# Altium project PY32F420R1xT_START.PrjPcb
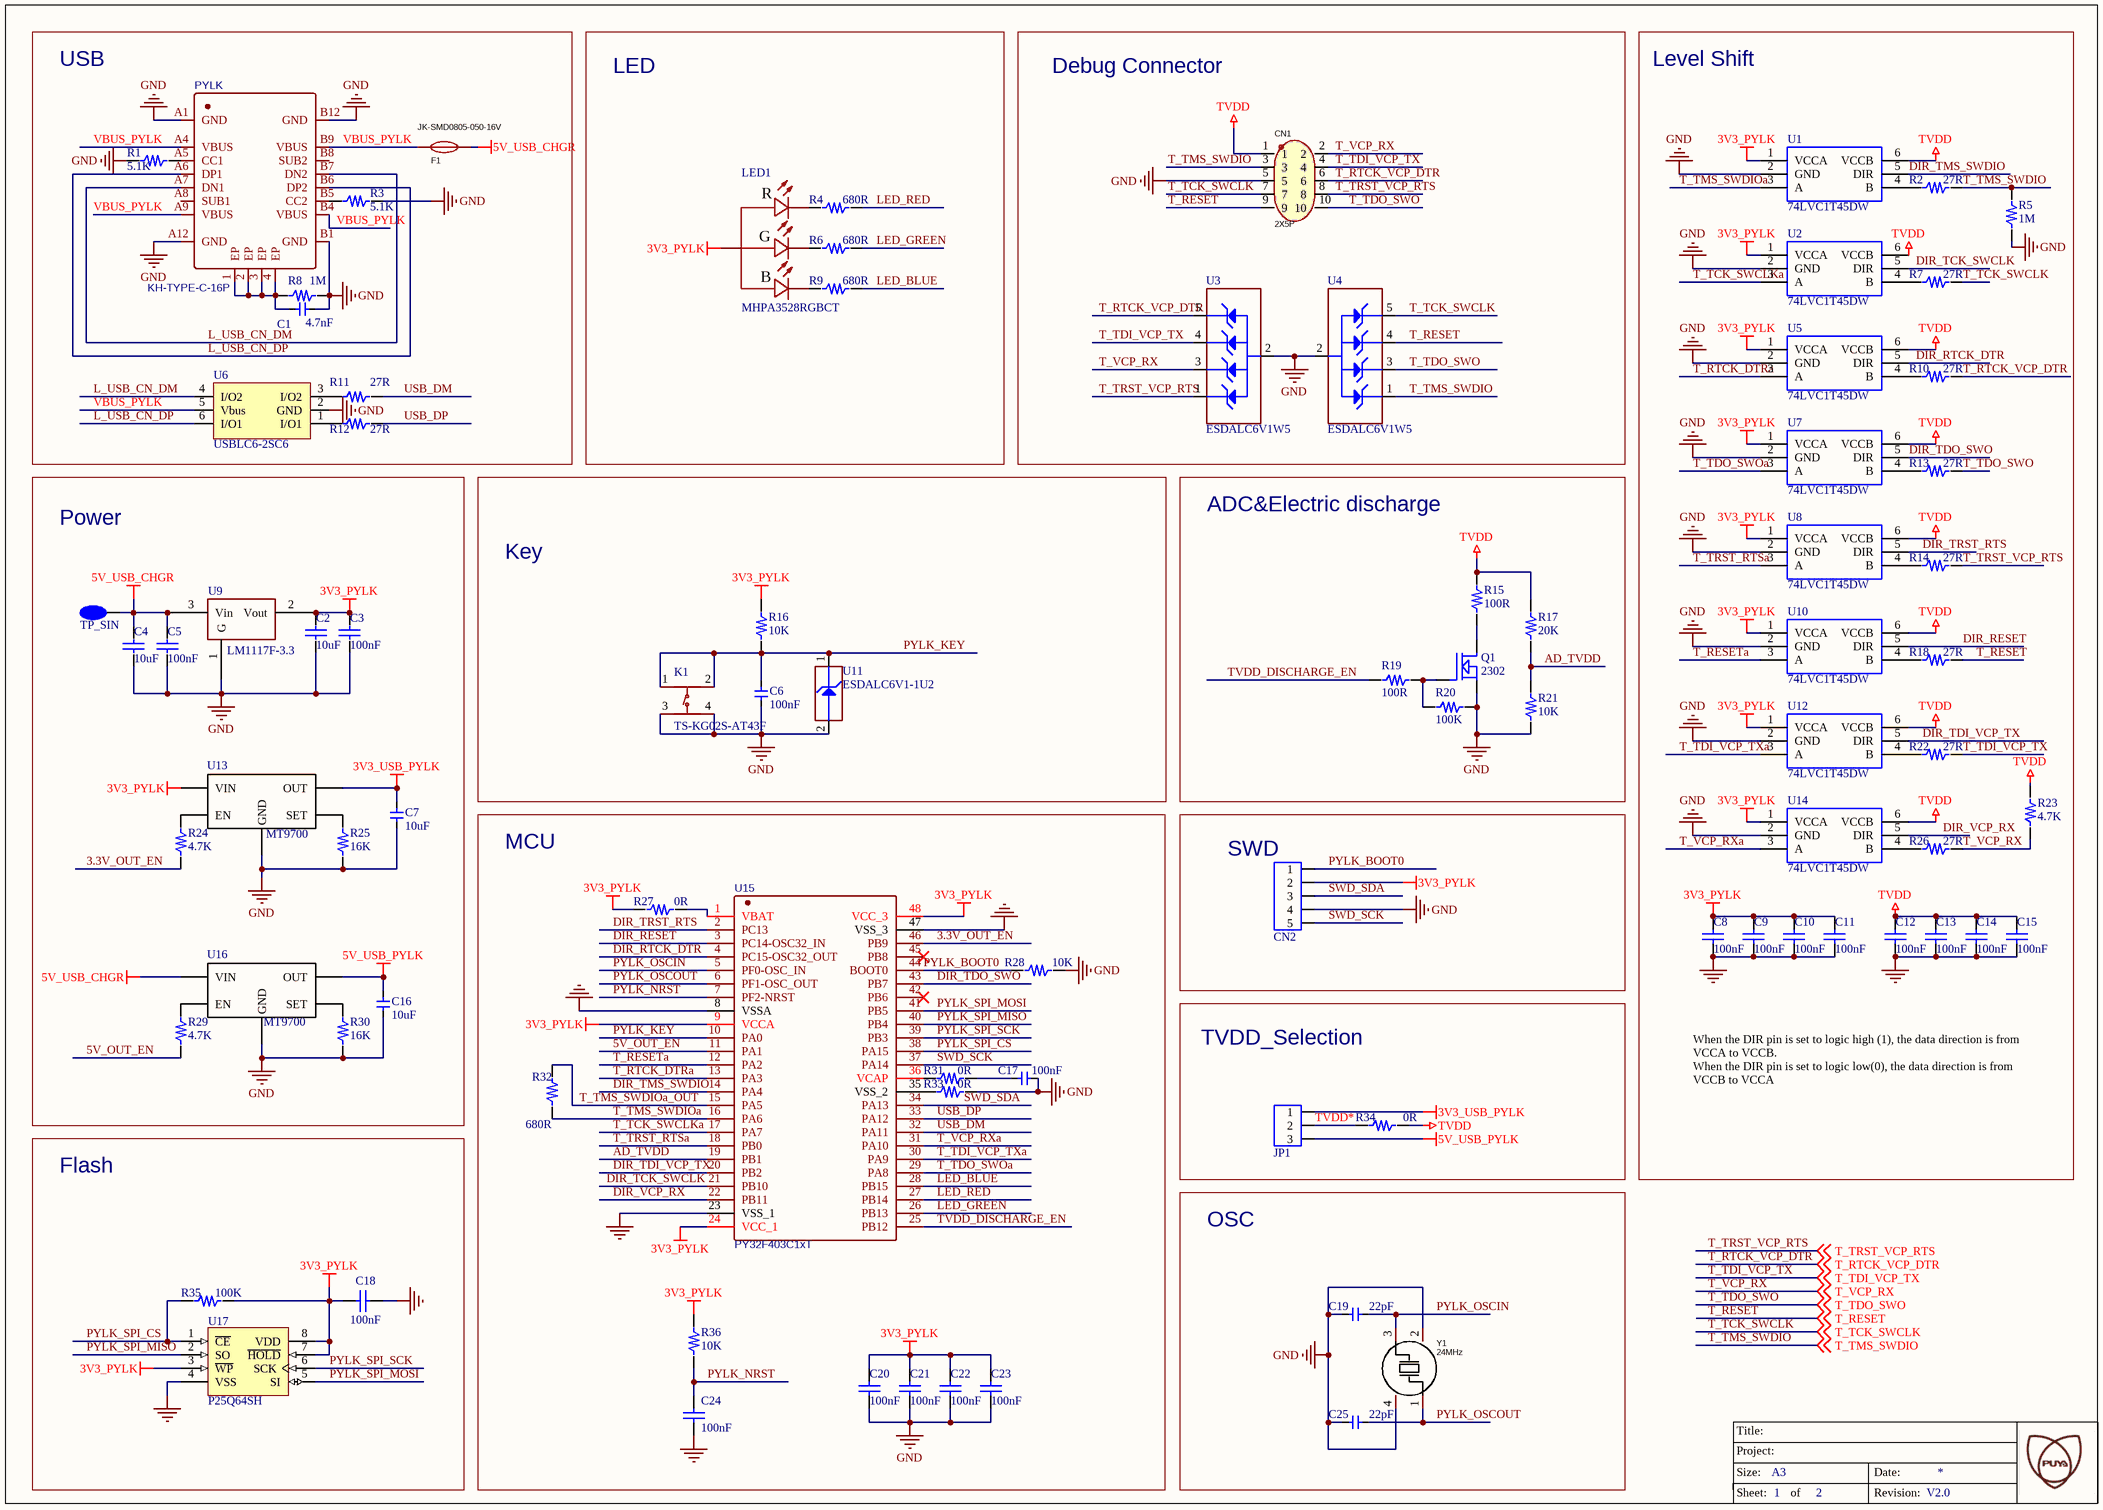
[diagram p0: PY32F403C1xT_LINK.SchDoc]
2 sheets, 144 parts. Net scope: global (net labels, ports and power ports of the same name join across sheets).
Board file: PY32F420R1xT_START.PcbDoc
Sheets:
  PY32F403C1xT_LINK.SchDoc
  PY32F420R1xT_START.SchDoc

## Sheet PY32F403C1xT_LINK.SchDoc: =DocumentName
size A3; Revision: V2.0; SheetNumber: 1; SheetTotal: 2; Project: PY32F420R1xT_START.PrjPcb

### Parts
5V_USB_CHGR  TP_SIN  [TP_SIN]
C1  4.7nF  [C0603]
C2  10uF  [C0805]
C3  100nF  [C0603]
C4  10uF  [C0805]
C5  100nF  [C0603]
C6  100nF  [C0603]
C7  10uF  [C0805]
C8  100nF  [C0603]
C9  100nF  [C0603]
C10  100nF  [C0603]
C11  100nF  [C0603]
C12  100nF  [C0603]
C13  100nF  [C0603]
C14  100nF  [C0603]
C15  100nF  [C0603]
C16  10uF  [C0805]
C17  100nF  [C0603]
C18  100nF  [C0603]
C19  22pF  [C0603]
C20  100nF  [C0603]
C21  100nF  [C0603]
C22  100nF  [C0603]
C23  100nF  [C0603]
C24  100nF  [C0603]
C25  22pF  [C0603]
CN1  2X5P  [HDR2X5]
CN2  CON5  [CON5]  (value not drawn)
F1  JK-SMD0805-050-16V  [F0805]
JP1  CON3  [CON3]  (value not drawn)
K1  TS-KG02S-AT43F  [SW-SMD_4P-L6.0-W6.0-P4.50-LS8.5]
LED1  MHPA3528RGBCT  [LED-ARRAY-SMD_4P-L3.5-W2.8-TL]
PYLK  KH-TYPE-C-16P  [USB-C-SMD_KH-TYPE-C-16P]
Q1  2302  [SOT23]
R1  5.1K  [R0603]
R2  27R  [R0603]
R3  5.1K  [R0603]
R4  680R  [R0603]
R5  1M  [R0603]
R6  680R  [R0603]
R7  27R  [R0603]
R8  1M  [R0603]
R9  680R  [R0603]
R10  27R  [R0603]
R11  27R  [R0603]
R12  27R  [R0603]
R13  27R  [R0603]
R14  27R  [R0603]
R15  100R  [R0805]
R16  10K  [R0603]
R17  20K  [R0603]
R18  27R  [R0603]
R19  100R  [R0603]
R20  100K  [R0603]
R21  10K  [R0603]
R22  27R  [R0603]
R23  4.7K  [R0603]
R24  4.7K  [R0603]
R25  16K  [R0603]
R26  27R  [R0603]
R27  0R  [JP2_SMD]
R28  10K  [R0603]
R29  4.7K  [R0603]
R30  16K  [R0603]
R31  0R  [JP2_SMD]
R32  680R  [R0603]
R33  0R  [JP2_SMD]
R34  0R  [JP2_SMD]
R35  100K  [R0603]
R36  10K  [R0603]
U1  74LVC1T45DW  [SOT363]
U2  74LVC1T45DW  [SOT363]
U3  ESDALC6V1W5  [ESD_SOT323-5L]
U4  ESDALC6V1W5  [ESD_SOT323-5L]
U5  74LVC1T45DW  [SOT363]
U6  USBLC6-2SC6  [SOT23-6]
U7  74LVC1T45DW  [SOT363]
U8  74LVC1T45DW  [SOT363]
U9  LM1117F-3.3  [SOT-89-3_L4.5-W2.5-P1.50-LS4.2-BR]
U10  74LVC1T45DW  [SOT363]
U11  ESDALC6V1-1U2  [ESD_ST0201]
U12  74LVC1T45DW  [SOT363]
U13  MT9700  [SOT23-5]
U14  74LVC1T45DW  [SOT363]
U15  PY32F403C1xT  [LQFP-48_L7.0-W7.0-P0.50-LS9.0-BL]
U16  MT9700  [SOT23-5]
U17  P25Q64SH  [SOP-8P]
Y1  24MHz  [CRYSTAL-SMD_4P-L3.2-W2.5-BL]

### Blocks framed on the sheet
USB: C1 F1 PYLK R1 R3 R8 R11 R12 U6
LED: LED1 R4 R6 R9
Debug Connector: CN1 U3 U4
Level Shift: C8-C15 R2 R5 R7 R10 R13 R14 R18 R22 R23 R26 U1 U2 U5 U7 U8 U10 U12 U14
Power: 5V_USB_CHGR C2-C5 C7 C16 R24 R25 R29 R30 U9 U13 U16
Key: C6 K1 R16 U11
ADC&Electric discharge: Q1 R15 R17 R19-R21
MCU: C17 C20-C24 R27 R28 R31-R33 R36 U15
SWD: CN2
TVDD_Selection: JP1 R34
Flash: C18 R35 U17
OSC: C19 C25 Y1

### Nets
3V3_PYLK: C2.2 C3.2 C8.2 C9.2 C10.2 C11.2 C18.2 C20.2 C21.2 C22.2 C23.2 CN2.2 LED1.1(-) R16.2 R27.1 R35.2 R36.2 U1.1(VCCA) U2.1(VCCA) U5.1(VCCA) U7.1(VCCA) U8.1(VCCA) U9.2(Vout) U10.1(VCCA) U12.1(VCCA) U13.5(VIN) U14.1(VCCA) U15.9(VCCA) U15.24(VCC_1) U15.48(VCC_3) U17.3(~{WP}) U17.7(~{HOLD}) U17.8(VDD)
3V3_USB_PYLK: C7.2 JP1.1 U13.1(OUT)
5V_USB_CHGR: 5V_USB_CHGR.1(TP_SIN) C4.2 C5.2 F1.2 U9.3(Vin) U16.5(VIN)
5V_USB_PYLK: C16.2 JP1.3 U16.1(OUT)
GND: C1.1 C2.1 C3.1 C4.1 C5.1 C6.1 C7.1 C8.1 C9.1 C10.1 C11.1 C12.1 C13.1 C14.1 C15.1 C16.1 C17.1 C18.1 C19.1 C20.1 C21.1 C22.1 C23.1 C24.1 C25.1 CN1.5 CN2.4 K1.3 K1.4 PYLK.A1(GND) PYLK.A12(GND) PYLK.B1(GND) PYLK.B12(GND) Q1.2(S) R1.1 R3.2 R5.1 R8.2 R20.1 R21.1 R25.1 R28.2 R30.1 R33.2 U1.2(GND) U2.2(GND) U3.2(GND) U4.2(GND) U5.2(GND) U6.2(GND) U7.2(GND) U8.2(GND) U9.1(G) U10.2(GND) U11.2(GND) U12.2(GND) U13.2(GND) U14.2(GND) U15.8(VSSA) U15.23(VSS_1) U15.47(VSS_3) U16.2(GND) U17.4(VSS) Y1.2(GND) Y1.4(GND)
TVDD: C12.2 C13.2 C14.2 C15.2 CN1.1 R15.2 R17.2 R23.2 R34.2 U1.6(VCCB) U2.6(VCCB) U5.6(VCCB) U7.6(VCCB) U8.6(VCCB) U10.6(VCCB) U12.6(VCCB) U14.6(VCCB)
3.3V_OUT_EN: R24.1 U15.46(PB9)
5V_OUT_EN: R29.1 U15.11(PA1)
AD_TVDD: R17.1 R21.2 U15.19(PB1)
DIR_RESET: U10.5(DIR) U15.3(PC14-OSC32_IN)
DIR_RTCK_DTR: U5.5(DIR) U15.4(PC15-OSC32_OUT)
DIR_TCK_SWCLK: U2.5(DIR) U15.21(PB10)
DIR_TDI_VCP_TX: U12.5(DIR) U15.20(PB2)
DIR_TDO_SWO: U7.5(DIR) U15.43(PB7)
DIR_TMS_SWDIO: U1.5(DIR) U15.14(PA4)
DIR_TRST_RTS: U8.5(DIR) U15.2(PC13)
DIR_VCP_RX: U14.5(DIR) U15.22(PB11)
L_USB_CN_DM: PYLK.A7(DN1) PYLK.B7(DN2) U6.4(I/O2)
L_USB_CN_DP: PYLK.A6(DP1) PYLK.B6(DP2) U6.6(I/O1)
LED_BLUE: R9.2 U15.28(PB15)
LED_GREEN: R6.2 U15.26(PB13)
LED_RED: R4.2 U15.27(PB14)
PYLK_BOOT0: CN2.1 R28.1 U15.44(BOOT0)
PYLK_KEY: C6.2 K1.1 K1.2 R16.1 U11.1(IO1) U15.10(PA0)
PYLK_NRST: C24.2 R36.1 U15.7(PF2-NRST)
PYLK_OSCIN: C19.2 U15.5(PF0-OSC_IN) Y1.3(OSC2)
PYLK_OSCOUT: C25.2 U15.6(PF1-OSC_OUT) Y1.1(OSC1)
PYLK_SPI_CS: R35.1 U15.38(PA15) U17.1(~{CE})
PYLK_SPI_MISO: U15.40(PB4) U17.2(SO)
PYLK_SPI_MOSI: U15.41(PB5) U17.5(SI)
PYLK_SPI_SCK: U15.39(PB3) U17.6(SCK)
SWD_SCK: CN2.5 U15.37(PA14)
SWD_SDA: CN2.3 U15.34(PA13)
T_RESET: CN1.9 R18.2 U4.4(IO3) ; off-sheet T_RESET
T_RESETa: U10.3(A) U15.12(PA2)
T_RTCK_DTRa: U5.3(A) U15.13(PA3)
T_RTCK_VCP_DTR: CN1.6 R10.2 U3.5(IO4) ; off-sheet T_RTCK_VCP_DTR
T_TCK_SWCLK: CN1.7 R7.2 U4.5(IO4) ; off-sheet T_TCK_SWCLK
T_TCK_SWCLKa: U2.3(A) U15.17(PA7)
T_TDI_VCP_TX: CN1.4 R22.2 U3.4(IO3) ; off-sheet T_TDI_VCP_TX
T_TDI_VCP_TXa: U12.3(A) U15.30(PA9)
T_TDO_SWO: CN1.10 R13.2 U4.3(IO2) ; off-sheet T_TDO_SWO
T_TDO_SWOa: U7.3(A) U15.29(PA8)
T_TMS_SWDIO: CN1.3 R2.2 R5.2 U4.1(IO1) ; off-sheet T_TMS_SWDIO
T_TMS_SWDIOa: R32.1 U1.3(A) U15.16(PA6)
T_TMS_SWDIOa_OUT: R32.2 U15.15(PA5)
T_TRST_RTSa: U8.3(A) U15.18(PB0)
T_TRST_VCP_RTS: CN1.8 R14.2 U3.1(IO1) ; off-sheet T_TRST_VCP_RTS
T_VCP_RX: CN1.2 R23.1 R26.2 U3.3(IO2) ; off-sheet T_VCP_RX
T_VCP_RXa: U14.3(A) U15.31(PA10)
TVDD*: JP1.2 R34.1
TVDD_DISCHARGE_EN: R19.2 U15.25(PB12)
USB_DM: R11.2 U15.32(PA11)
USB_DP: R12.2 U15.33(PA12)
VBUS_PYLK: F1.1 PYLK.A4(VBUS) PYLK.A9(VBUS) PYLK.B4(VBUS) PYLK.B9(VBUS) U6.5(Vbus)
NetC1_2: C1.2 PYLK.1(EP) PYLK.2(EP) PYLK.3(EP) PYLK.4(EP) R8.1
NetC17_2: C17.2 R31.2
NetLED1_2: LED1.2(-) R9.1
NetLED1_3: LED1.3(-) R6.1
NetLED1_4: LED1.4(-) R4.1
NetPYLK_A5: PYLK.A5(CC1) R1.2
NetPYLK_B5: PYLK.B5(CC2) R3.1
NetQ1_1: Q1.1(G) R19.1 R20.2
NetQ1_3: Q1.3(D) R15.1
NetR2_1: R2.1 U1.4(B)
NetR7_1: R7.1 U2.4(B)
NetR10_1: R10.1 U5.4(B)
NetR11_1: R11.1 U6.3(I/O2)
NetR12_1: R12.1 U6.1(I/O1)
NetR13_1: R13.1 U7.4(B)
NetR14_1: R14.1 U8.4(B)
NetR18_1: R18.1 U10.4(B)
NetR22_1: R22.1 U12.4(B)
NetR24_2: R24.2 U13.4(EN)
NetR25_2: R25.2 U13.3(SET)
NetR26_1: R26.1 U14.4(B)
NetR27_2: R27.2 U15.1(VBAT)
NetR29_2: R29.2 U16.4(EN)
NetR30_2: R30.2 U16.3(SET)
NetR31_1: R31.1 U15.36(VCAP)
NetR33_1: R33.1 U15.35(VSS_2)

Not connected (* = marked no-connect by the designer): PYLK A8(SUB1) B8(SUB2); U15 42(PB6)* 45(PB8)*

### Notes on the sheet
- When the DIR pin is set to logic high (1), the data direction is from VCCA to VCCB.
  When the DIR pin is set to logic low(0), the data direction is from VCCB to VCCA

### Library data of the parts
C1 C3 C5 C6 C17 C19 C25 = C0603: PCB DECAL: 0603
C2 C4 C7 C16 = C0805: PCB DECAL: 0805
C8-C15 C18 C20-C24 = 贴片高压陶瓷电容: Capacitor (Semiconductor SIM Model); 器件封装(外观): 0603; Value: 104
CN1 = 2X5P: Manufacturer: XFCN(兴飞); Symbol: PZ254V-12-10P; Add into BOM: yes; Pitch: 2.54mm; Circluar Pins/Square Pins: 方针
F1 = JK-SMD0805-050-16V: Manufacturer: JK(金科); Add into BOM: yes; Voltage - Max: 6V; Current - Max: 100A; Hold Current: 500mA; Trip Current: 1A; Power Dissipation: 600mW; Resistance - Initial (Ri) (Min): 150mΩ; Resistance - Post Trip (R1) (Max): 850mΩ; Time to Trip(Max): 100ms
K1 = TS-KG02S-AT43F: Manufacturer: HANBO(汉博); Add into BOM: yes; Circuit: 单刀单掷; Actuator Style: 圆形按钮; Operating Force: 250gf; Switch Length: 6mm; Switch Height: 4.3mm; Strike Gundam: 不带; Contact Current: 50mA; Voltage Rating (DC): 12V; Insulation Resistance: 100MΩ; Actuator/Cap Color: 黑色; Pin Style: 鸥翼型
LED1 = MHPA3528RGBCT: Manufacturer: MEIHUA(美华); Add into BOM: yes
PYLK = KH-TYPE-C-16P: BOM_Manufacturer: Shenzhen Kinghelm Elec; Contributor: LCSC
Q1 = MOSFET N: Value: SI2302
R1-R14 R16-R24 R26-R29 R31-R36 = R0603: PCB DECAL: 0603
R15 = R0805: PCB DECAL: 0805
R25 R30 = R0603_7: 0603WAF1602T5E 16KΩ(1602) ±1%; PCB DECAL: 0603
U3 U4 = ESDALC6V1W5: Dual Transil array for ESD protection; Internal_Part_Number: MCD-00136; Part_Type: Diode; Manufacturer: STMICROELECTRONICS; ECCN_US: EAR99; ECCN_EU: NEC; Provided_By: Subcon; Initial_Board_Reference: MB1262
U6 = USBLC6-2SC6: Function: ESD EMI fliter
U11 = ESDALC6V1-1U2: ESD protection 6V1; Internal_Part_Number: MCD-00170; Part_Type: Diode; Manufacturer: STMICROELECTRONICS; ECCN_US: EAR99; ECCN_EU: NEC; Provided_By: Subcon; Initial_Board_Reference: MB1274
U15 = PY32F403C1xT: LQFP48; BOM_Manufacturer: PUYA(普冉)
U17 = SST25VF010: Value: SST25VF020B; 器件封装(外观): SOP8
Y1 = ABM8AIG-24.000MHZ-82Z-T: ±20ppm , 12.5pF , T_use: -40°C~125°C; Manufacturer: ABRACON; Add into BOM: yes; External load capacitor: 8pF; Frequency Stability(Full temperature range): ±50ppm; Equivalent Series Resistance (ESR): 50Ω

## Sheet PY32F420R1xT_START.SchDoc: =DocumentName
size A3; Revision: V2.0; SheetNumber: 2; SheetTotal: 2; Project: PY32F420R1xT_START.PrjPcb
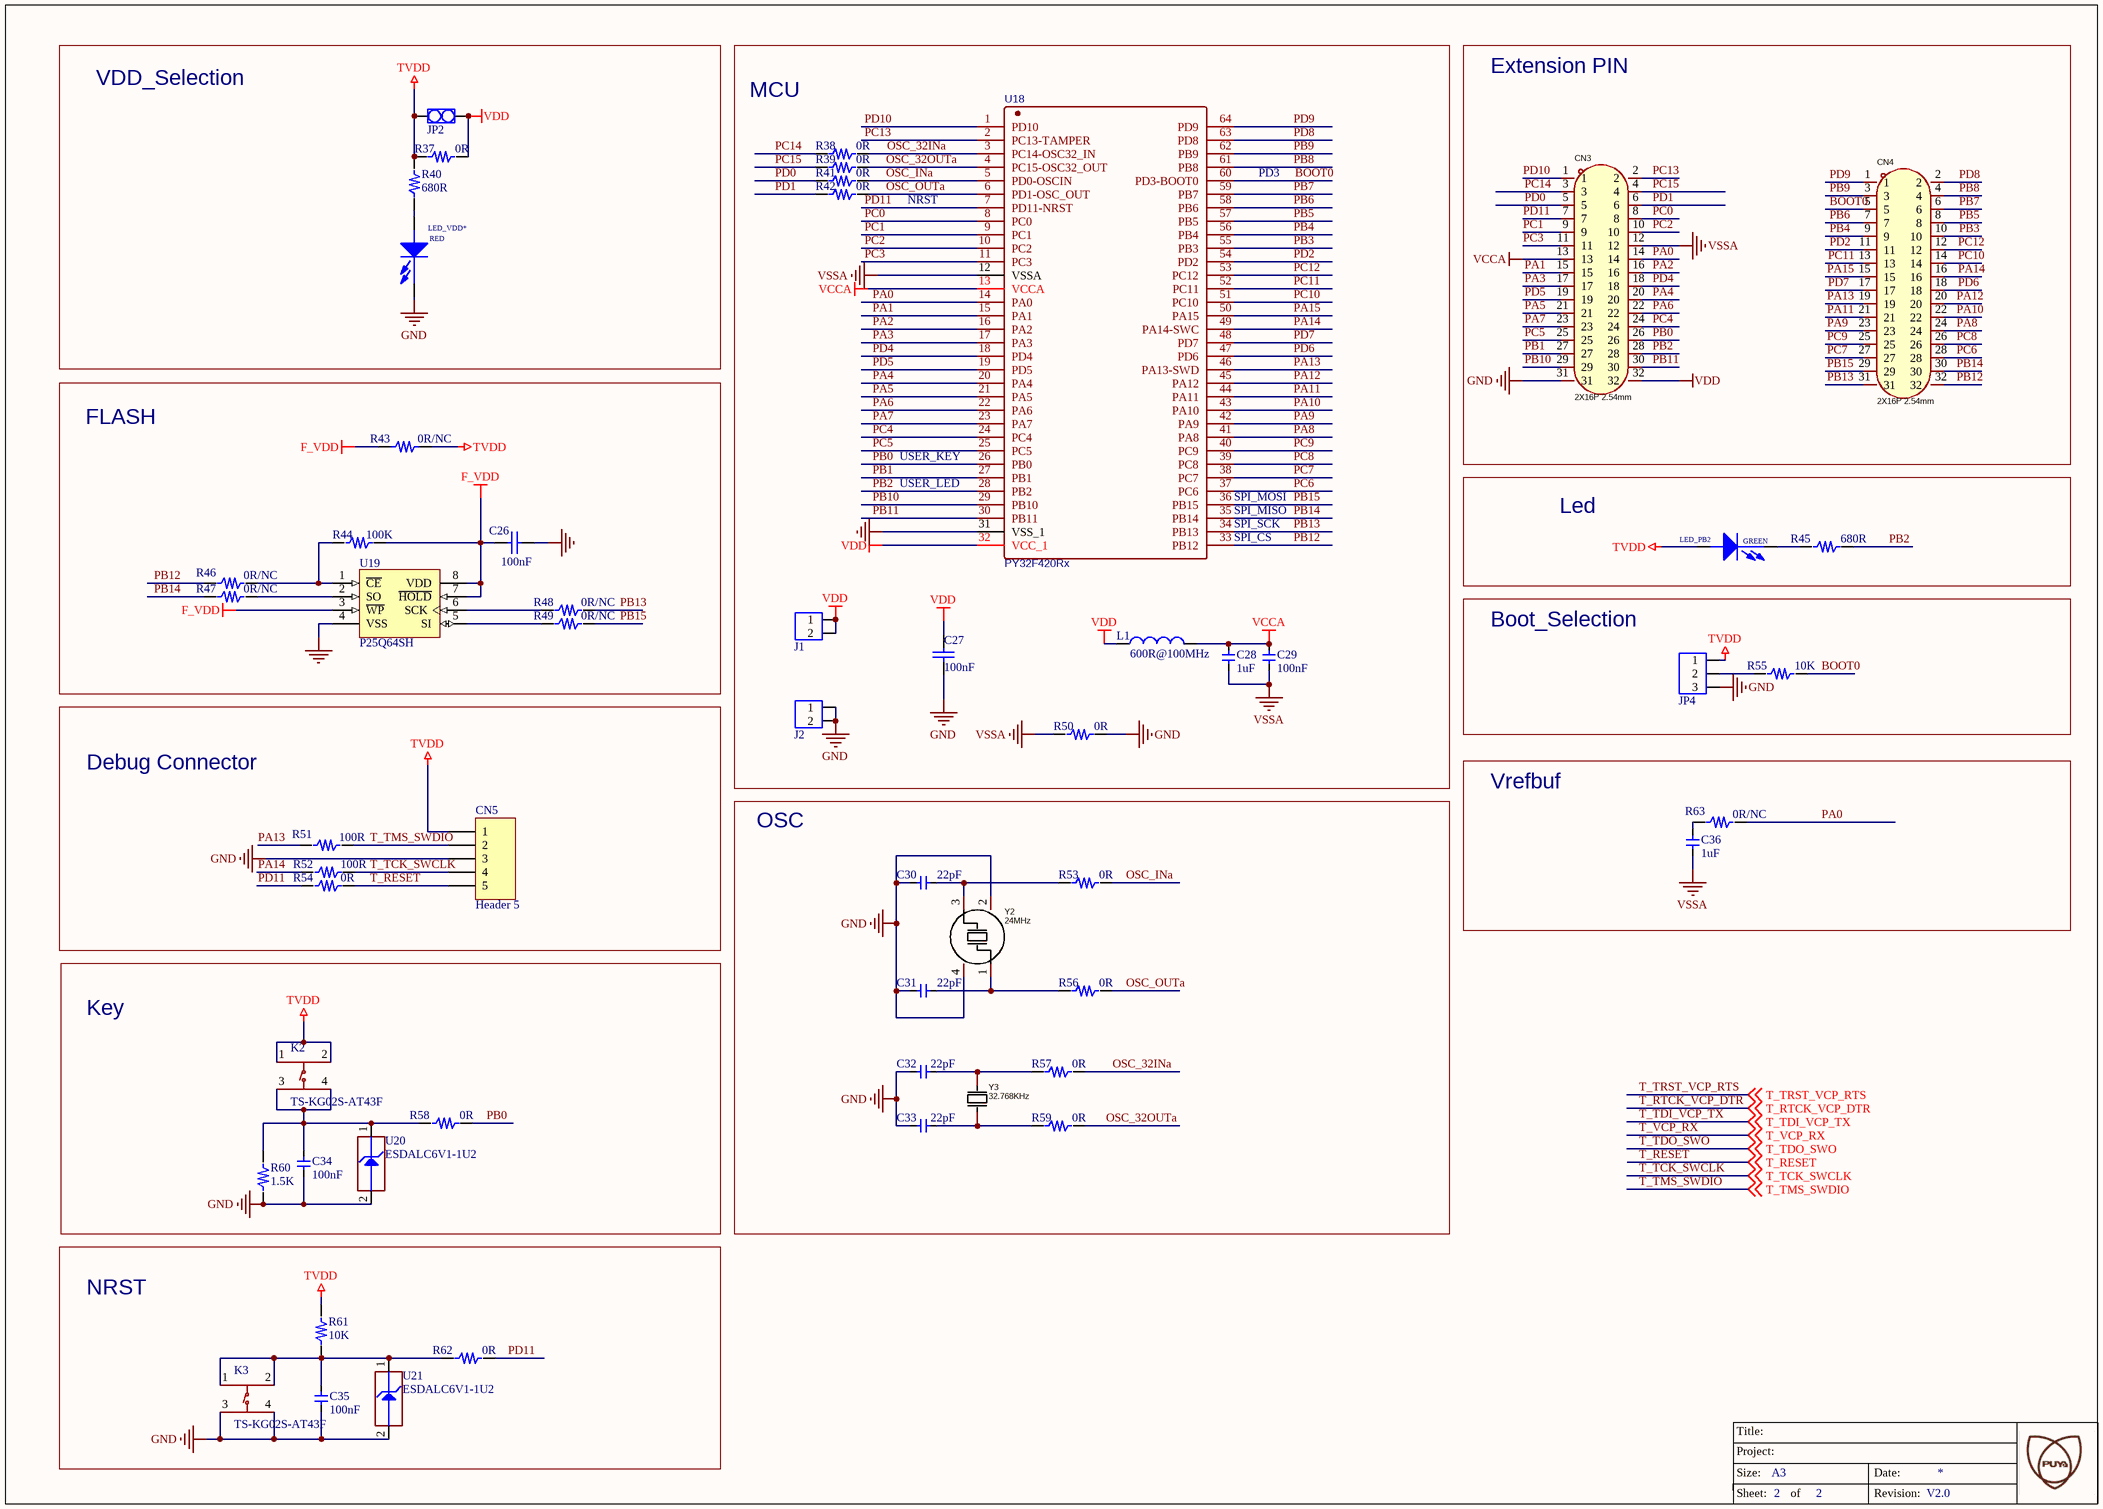
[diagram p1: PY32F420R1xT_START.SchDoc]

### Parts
C26  100nF  [C0603]
C27  100nF  [C0603]
C28  1uF  [C0603]
C29  100nF  [C0603]
C30  22pF  [C0603]
C31  22pF  [C0603]
C32  22pF  [C0603]
C33  22pF  [C0603]
C34  100nF  [C0603]
C35  100nF  [C0603]
C36  1uF  [C0603]
CN3  2X16P 2.54mm  [HDR-TH_32P-P2.54-V-M-R2-C16-S2.54-3]
CN4  2X16P 2.54mm  [HDR-TH_32P-P2.54-V-M-R2-C16-S2.54-3]
CN5  Header 5  [HDR1X5]
J1  CON2  [CON2]  (value not drawn)
J2  CON2  [CON2]  (value not drawn)
JP2  CON2  [CON2]  (value not drawn)
JP4  CON3  [CON3]  (value not drawn)
K2  TS-KG02S-AT43F  [SW-SMD_4P-L6.0-W6.0-P4.50-LS8.5]
K3  TS-KG02S-AT43F  [SW-SMD_4P-L6.0-W6.0-P4.50-LS8.5]
L1  value 600R@100MHz  [L0603]  (hidden comment: BEAD)
LED_PB2  GREEN  [0603_LED]
LED_VDD*  RED  [0603_LED]
R37  0R  [JP2_SMD]
R38  0R  [JP2_SMD]
R39  0R  [JP2_SMD]
R40  680R  [R0603]
R41  0R  [JP2_SMD]
R42  0R  [JP2_SMD]
R43  0R/NC  [JP2_SMD]
R44  100K  [R0603]
R45  680R  [R0603]
R46  0R/NC  [JP2_SMD]
R47  0R/NC  [JP2_SMD]
R48  0R/NC  [JP2_SMD]
R49  0R/NC  [JP2_SMD]
R50  0R  [R0603]
R51  100R  [JP2_SMD]
R52  100R  [JP2_SMD]
R53  0R  [JP2_SMD]
R54  0R  [JP2_SMD]
R55  10K  [R0603]
R56  0R  [JP2_SMD]
R57  0R  [JP2_SMD]
R58  0R  [JP2_SMD]
R59  0R  [JP2_SMD]
R60  1.5K  [R0603]
R61  10K  [R0603]
R62  0R  [JP2_SMD]
R63  0R/NC  [JP2_SMD]
U18  PY32F420Rx  [LQFP-64_L10.0-W10.0-P0.50-LS12.0-BL]
U19  P25Q64SH  [SOP-8P]
U20  ESDALC6V1-1U2  [ESD_ST0201]
U21  ESDALC6V1-1U2  [ESD_ST0201]
Y2  24MHz  [CRYSTAL-SMD_4P-L3.2-W2.5-BL]
Y3  32.768KHz  [CRYSTAL-SMD_L3.2-W1.5-1]

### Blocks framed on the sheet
VDD_Selection: JP2 LED_VDD* R37 R40
MCU: C27-C29 J1 J2 L1 R38 R39 R41 R42 R50 U18
Extension PIN: CN3 CN4
FLASH: C26 R43 R44 R46-R49 U19
Led: LED_PB2 R45
Boot_Selection: JP4 R55
Debug Connector: CN5 R51 R52 R54
Vrefbuf: C36 R63
OSC: C30-C33 R53 R56 R57 R59 Y2 Y3
Key: C34 K2 R58 R60 U20
NRST: C35 K3 R61 R62 U21

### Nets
F_VDD: C26.2 R43.2 R44.2 U19.3(~{WP}) U19.7(~{HOLD}) U19.8(VDD)
GND: C26.1 C27.1 C30.1 C31.1 C32.1 C33.1 C34.1 C35.1 CN3.31 CN5.3 J2.1 J2.2 JP4.3 K3.3 K3.4 LED_VDD*.2(CATHODE) R50.2 R60.1 U18.31(VSS_1) U19.4(VSS) U20.2(GND) U21.2(GND) Y2.2(GND) Y2.4(GND)
TVDD: CN5.1 JP2.1 JP4.1 K2.1 K2.2 LED_PB2.1(ANODE) R37.1 R40.2 R43.1 R61.1
VCCA: C28.2 C29.2 CN3.13 L1.2 U18.13(VCCA)
VDD: C27.2 CN3.32 J1.1 J1.2 JP2.2 L1.1 R37.2 U18.32(VCC_1)
VSSA: C28.1 C29.1 C36.1 CN3.12 R50.1 U18.12(VSSA)
BOOT0: CN4.5 R55.2 U18.60(PD3-BOOT0)
OSC_32INa: R38.2 R57.2 U18.3(PC14-OSC32_IN)
OSC_32OUTa: R39.2 R59.2 U18.4(PC15-OSC32_OUT)
OSC_INa: R41.2 R53.2 U18.5(PD0-OSCIN)
OSC_OUTa: R42.2 R56.2 U18.6(PD1-OSC_OUT)
PA0: CN3.14 R63.1 U18.14(PA0)
PA1: CN3.15 U18.15(PA1)
PA2: CN3.16 U18.16(PA2)
PA3: CN3.17 U18.17(PA3)
PA4: CN3.20 U18.20(PA4)
PA5: CN3.21 U18.21(PA5)
PA6: CN3.22 U18.22(PA6)
PA7: CN3.23 U18.23(PA7)
PA8: CN4.24 U18.41(PA8)
PA9: CN4.23 U18.42(PA9)
PA10: CN4.22 U18.43(PA10)
PA11: CN4.21 U18.44(PA11)
PA12: CN4.20 U18.45(PA12)
PA13: CN4.19 R51.2 U18.46(PA13-SWD)
PA14: CN4.16 R52.2 U18.49(PA14-SWC)
PA15: CN4.15 U18.50(PA15)
PB0: CN3.26 R58.2 U18.26(PB0)
PB1: CN3.27 U18.27(PB1)
PB2: CN3.28 R45.2 U18.28(PB2)
PB3: CN4.10 U18.55(PB3)
PB4: CN4.9 U18.56(PB4)
PB5: CN4.8 U18.57(PB5)
PB6: CN4.7 U18.58(PB6)
PB7: CN4.6 U18.59(PB7)
PB8: CN4.4 U18.61(PB8)
PB9: CN4.3 U18.62(PB9)
PB10: CN3.29 U18.29(PB10)
PB11: CN3.30 U18.30(PB11)
PB12: CN4.32 R46.2 U18.33(PB12)
PB13: CN4.31 R48.1 U18.34(PB13)
PB14: CN4.30 R47.2 U18.35(PB14)
PB15: CN4.29 R49.1 U18.36(PB15)
PC0: CN3.8 U18.8(PC0)
PC1: CN3.9 U18.9(PC1)
PC2: CN3.10 U18.10(PC2)
PC3: CN3.11 U18.11(PC3)
PC4: CN3.24 U18.24(PC4)
PC5: CN3.25 U18.25(PC5)
PC6: CN4.28 U18.37(PC6)
PC7: CN4.27 U18.38(PC7)
PC8: CN4.26 U18.39(PC8)
PC9: CN4.25 U18.40(PC9)
PC10: CN4.14 U18.51(PC10)
PC11: CN4.13 U18.52(PC11)
PC12: CN4.12 U18.53(PC12)
PC13: CN3.2 U18.2(PC13-TAMPER)
PC14: CN3.3 R38.1
PC15: CN3.4 R39.1
PD0: CN3.5 R41.1
PD1: CN3.6 R42.1
PD2: CN4.11 U18.54(PD2)
PD4: CN3.18 U18.18(PD4)
PD5: CN3.19 U18.19(PD5)
PD6: CN4.18 U18.47(PD6)
PD7: CN4.17 U18.48(PD7)
PD8: CN4.2 U18.63(PD8)
PD9: CN4.1 U18.64(PD9)
PD10: CN3.1 U18.1(PD10)
PD11: CN3.7 R54.2 R62.2 U18.7(PD11-NRST)
T_RESET: CN5.5 R54.1 ; off-sheet T_RESET
T_TCK_SWCLK: CN5.4 R52.1 ; off-sheet T_TCK_SWCLK
T_TMS_SWDIO: CN5.2 R51.1 ; off-sheet T_TMS_SWDIO
NetC30_2: C30.2 R53.1 Y2.3(OSC2)
NetC31_2: C31.2 R56.1 Y2.1(OSC1)
NetC32_2: C32.2 R57.1 Y3.2(OSC2)
NetC33_2: C33.2 R59.1 Y3.1(OSC1)
NetC34_2: C34.2 K2.3 K2.4 R58.1 R60.2 U20.1(IO1)
NetC35_2: C35.2 K3.1 K3.2 R61.2 R62.1 U21.1(IO1)
NetC36_2: C36.2 R63.2
NetJP4_2: JP4.2 R55.1
NetLED_PB2_2: LED_PB2.2(CATHODE) R45.1
NetLED_VDD*_1: LED_VDD*.1(ANODE) R40.1
NetR44_1: R44.1 R46.1 U19.1(~{CE})
NetR47_1: R47.1 U19.2(SO)
NetR48_2: R48.2 U19.6(SCK)
NetR49_2: R49.2 U19.5(SI)

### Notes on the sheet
- (near U18) PD3
- NRST
- USER_KEY
- USER_LED
- (near U18) SPI_MISO
- (near U18) SPI_MOSI
- (near U18) SPI_CS
- (near U18) SPI_SCK

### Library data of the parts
C26 C27 = 贴片高压陶瓷电容: as C8 on sheet PY32F403C1xT_LINK
C28-C36 = C0603: PCB DECAL: 0603
CN3 CN4 = 2X16P 2.54mm: Manufacturer: XKB Connection(中国星坤); Symbol: X6522WV-2X16H-C60D30-E80; Add into BOM: yes; Circluar Pins/Square Pins: 方针; Current Rating (Max): 3A; Voltage Rating (Max): 250V; Soldering Temperature(Max): 260℃
CN5 = Header 5: Header, 5-Pin
JP2 = CON2_DIP
K2 K3 = TS-KG02S-AT43F: as K1 on sheet PY32F403C1xT_LINK
L1 = BEAD: SMD Chip ferrite bead, 600R@100MHz +/-25%, 350mA, 500mohm DC, 0603, T=0.8mm; Internal_Part_Number: MCD-00047; Part_Type: Inductor; Manufacturer_Part_Number: FCM1608KF-601T03; Manufacturer: TAI-TECH; Provided_By: SUBCO
LED_PB2 LED_VDD* = PDI-E803_Dup1
R37-R63 = R0603: PCB DECAL: 0603
U18 = PY32F420Rx_1: LQFP64; BOM_Manufacturer: PUYA(普冉); BOM_Manufacturer Part: PY32CA00R1x
U19 = SST25VF010: Value: SST25VF020B; 器件封装(外观): SOP8
U20 U21 = ESDALC6V1-1U2: as U11 on sheet PY32F403C1xT_LINK
Y2 = ABM8AIG-24.000MHZ-82Z-T: as Y1 on sheet PY32F403C1xT_LINK
Y3 = XKXGI-SUA-32.768K: ±20ppm , 12.5pF , T_use: -40°C~125°C; Manufacturer: YXC(扬兴晶振); Add into BOM: yes; Crystal Type: 贴片晶振; Frequency Stability(Full temperature range): ±30ppm

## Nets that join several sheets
GND: PY32F403C1xT_LINK (65 pins), PY32F420R1xT_START (24 pins)
TVDD: PY32F403C1xT_LINK (17 pins), PY32F420R1xT_START (10 pins)
T_RESET: PY32F403C1xT_LINK (CN1.9 R18.2 U4.4), PY32F420R1xT_START (CN5.5 R54.1)
T_TCK_SWCLK: PY32F403C1xT_LINK (CN1.7 R7.2 U4.5), PY32F420R1xT_START (CN5.4 R52.1)
T_TMS_SWDIO: PY32F403C1xT_LINK (CN1.3 R2.2 R5.2 U4.1), PY32F420R1xT_START (CN5.2 R51.1)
